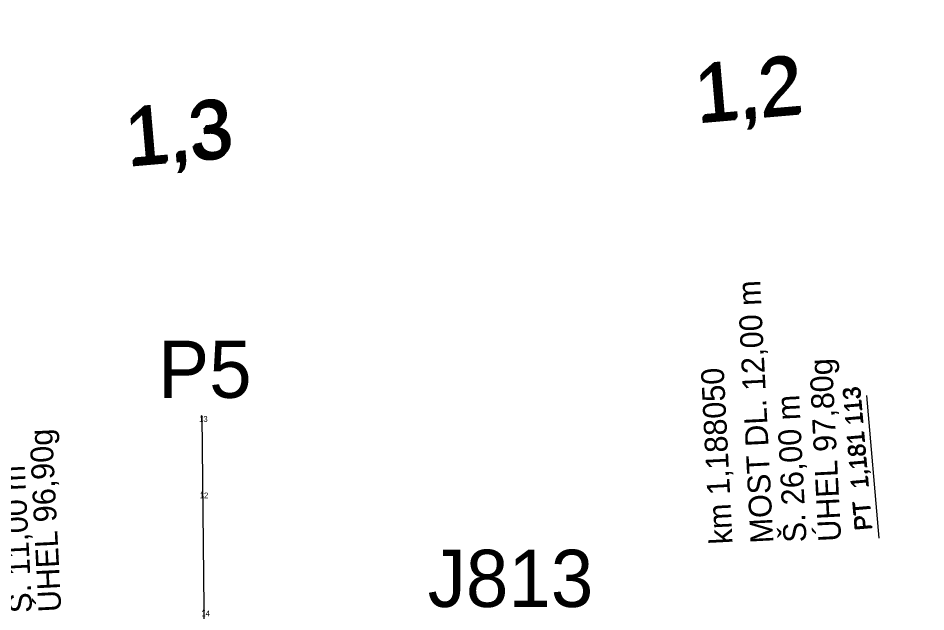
# Model space of a CAD drawing. Extents: x -606444 to -604546, y -1158114 to -1156869.
# Drawn here: x -606032.4 to -605873.5, y -1157252.5 to -1157148.6 of the extents above; entities that cross this region are included whole.
import ezdxf

# ---------------------------------------------------------------- set-up
doc = ezdxf.new("R2010")
doc.units = 0
for name, color, linetype in [('ARCHIVNÍ SONDY', 7, 'Continuous'), ('geofyzikální profily_předběžný GTP', 7, 'Continuous'), ('NS_VB_POP', 7, 'Continuous'), ('OSAPOP', 7, 'Continuous')]:
    doc.layers.add(name, color=color, linetype=linetype)

msp = doc.modelspace()

# ---------------------------------------------------------------- linework, layer by layer
for p, q in [((-606000.27, -1157218.22), (-606000.37, -1157218.12)), ((-606000.27, -1157218.22), (-606000.37, -1157218.32)), ((-606000.27, -1157218.22), (-606000.17, -1157218.12)), ((-606000.27, -1157218.22), (-606000.17, -1157218.32)), ((-606000.16, -1157231.6), (-606000.26, -1157231.5)), ((-606000.16, -1157231.6), (-606000.26, -1157231.7)), ((-606000.16, -1157231.6), (-606000.06, -1157231.5)), ((-606000.16, -1157231.6), (-606000.06, -1157231.7)), ((-605999.89, -1157252.24), (-605999.99, -1157252.14)), ((-605999.89, -1157252.24), (-605999.99, -1157252.34)), ((-605999.89, -1157252.24), (-605999.79, -1157252.14)), ((-605999.89, -1157252.24), (-605999.79, -1157252.34))]:
    msp.add_line(p, q)
at = {"layer": 'geofyzikální profily_předběžný GTP'}
msp.add_lwpolyline([(-606000.25, -1157218.24), (-605999.1, -1157330.17)], dxfattribs=at)
msp.add_spline([(-605950.45, -1157295.92), (-605904.87, -1157291.72), (-605856.97, -1157287.39), (-605826.74, -1157281.64), (-605800.72, -1157271.74), (-605782.37, -1157261.31), (-605766.27, -1157249.35), (-605744.49, -1157228.62), (-605716.54, -1157200.55), (-605701.17, -1157186.19), (-605682.49, -1157172.86), (-605668.89, -1157164.85), (-605653.7, -1157158.02), (-605640.64, -1157153.35), (-605624.44, -1157148.58)], degree=3, dxfattribs=at)
at = {"layer": 'OSAPOP'}
msp.add_line((-605881.7, -1157239.55), (-605883.85, -1157214.64), dxfattribs=at)

# ---------------------------------------------------------------- texts
for s, p in [('13', (-606000.72, -1157219.22)), ('12', (-606000.61, -1157232.6)), ('14', (-606000.34, -1157253.24))]:
    msp.add_text(s, height=1).set_placement(p)
at = {"layer": 'ARCHIVNÍ SONDY'}
msp.add_text('J813', height=10, dxfattribs=at).set_placement((-605960.72, -1157251.61))
at = {"layer": 'geofyzikální profily_předběžný GTP'}
msp.add_text('P5', height=10, dxfattribs=at).set_placement((-606007.89, -1157215.02))
at = {"layer": 'NS_VB_POP'}
for s, p in [('MOST DL. 12,00 m', (-605900.2, -1157240.39)), ('ÚHEL 97,80g', (-605888.33, -1157240.09)), ('km 1,188050', (-605907.34, -1157240.55)), ('Š. 26,00 m', (-605894.4, -1157240.24)), ('ÚHEL 96,90g', (-606024.84, -1157252.42)), ('Š. 11,00 m', (-606029.95, -1157252.57))]:
    msp.add_text(s, height=4, rotation=92.9074, dxfattribs=at).set_placement(p)
at = {"layer": 'OSAPOP'}
for s, height, rotation, p in [('1,2', 10, 4.9211, (-605913.59, -1157167.01)), ('1,2', 10, 4.9211, (-605913.46, -1157166.85)), ('1,2', 10, 4.9211, (-605913.32, -1157166.69)), ('1,2', 10, 4.9211, (-605913.19, -1157166.53)), ('1,3', 10, 4.9211, (-606013.04, -1157174.27)), ('1,3', 10, 4.9211, (-606012.9, -1157174.11)), ('1,3', 10, 4.9211, (-606013.31, -1157174.6)), ('1,3', 10, 4.9211, (-606013.18, -1157174.43)), ('PT  1,181 113', 3, 94.9211, (-605882.99, -1157238)), ('PT  1,181 113', 3, 94.9211, (-605882.83, -1157238.14))]:
    msp.add_text(s, height=height, rotation=rotation, dxfattribs=at).set_placement(p)

doc.saveas('drawing.dxf')
